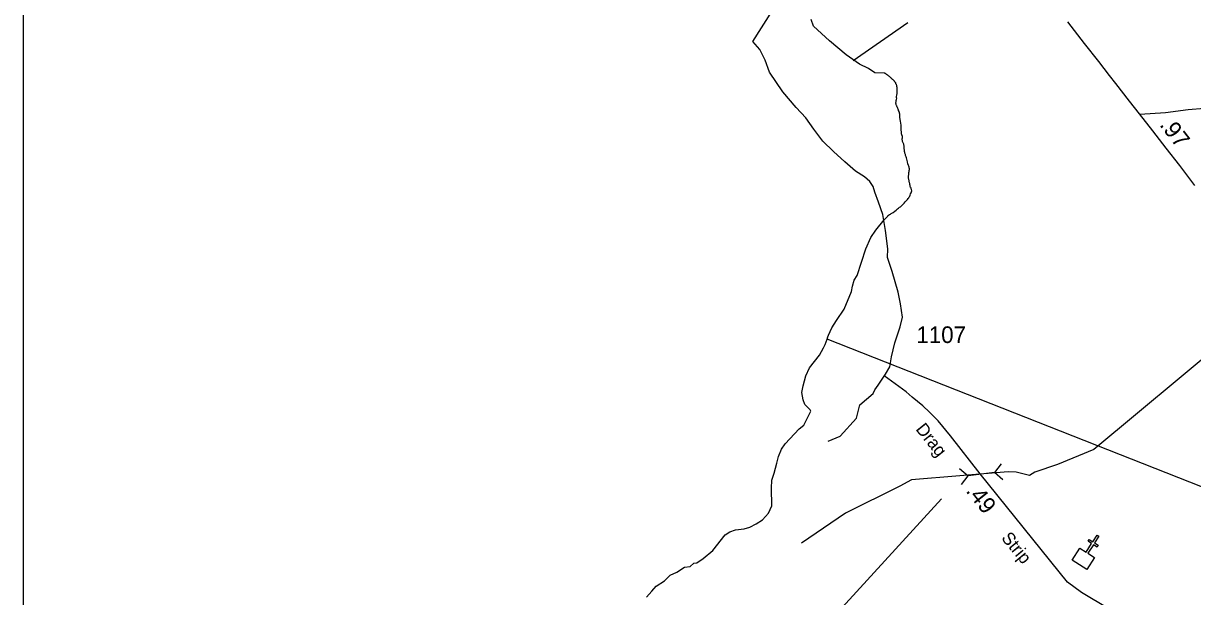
# Model space of a CAD drawing. Extents: x 2082433 to 2279600, y 546599 to 755198.
# Drawn here: x 2133614 to 2142394, y 575060 to 579366 of the extents above; entities that cross this region are included whole.
import ezdxf

# ---------------------------------------------------------------- set-up
doc = ezdxf.new("R2010")
doc.units = 0
for name, color, linetype in [('Exist Boundary Political CountyLine', 7, 'Continuous'), ('Exist Boundary Political Fire Districts', 7, 'Continuous'), ('Exist Cultural Church CELL', 7, 'Continuous'), ('Exist Hydrographic Creek Single Shore', 7, 'Continuous'), ('Exist Road Non-System Type 51', 7, 'Continuous'), ('Exist Road Primary NC Attributed', 7, 'Continuous'), ('Exist Road Primary NC Service Mileage Hundredths English Label', 7, 'Continuous'), ('Exist Road Secondary Mileage Hundredths English Label', 7, 'Continuous'), ('Exist Road Secondary Structure Culvert CELL', 7, 'Continuous'), ('Exist Road Secondary Structure Culvert Number Label', 7, 'Continuous'), ('Exist Road Secondary Type 51 Attributed', 7, 'Continuous'), ('Exist Road Secondary Type 51 Label', 7, 'Continuous'), ('Exist Road Secondary Type 51 Number Label', 7, 'Continuous'), ('Map Preparation Inset Cut Line', 7, 'Continuous')]:
    doc.layers.add(name, color=color, linetype=linetype)

msp = doc.modelspace()

# ---------------------------------------------------------------- linework, layer by layer
at = {"layer": 'Exist Boundary Political CountyLine'}
for points in [[(2139994.3, 578141.5), (2139970.9, 578177.9), (2139929.3, 578214.3), (2139862.6, 578255.7), (2139782.5, 578326.1), (2139696.7, 578404.1), (2139616.2, 578482.1), (2139548.6, 578570.5), (2139488.9, 578656.3), (2139416.1, 578734.3), (2139317.4, 578851.3), (2139216, 578999.5), (2139184.8, 579090.5), (2139143.3, 579168.5), (2139092.6, 579230.9), (2139238.1, 579462.3)], [(2140086.6, 576731), (2140119, 576786.9), (2140132, 576862.3), (2140158, 576966.3), (2140196.9, 577085.9), (2140215.1, 577158.7), (2140200.8, 577260.1), (2140182.6, 577345.9), (2140138.5, 577501.9), (2140103.4, 577608.5), (2140106, 577673.5), (2140087.8, 577811.3), (2140067, 577930.9), (2140035.8, 578021.9), (2140007.2, 578097.3), (2139994.3, 578141.5)], [(2139657.6, 576226.7), (2139746.8, 576266.1), (2139870.1, 576400.1), (2139895.1, 576499.9), (2139994.4, 576586.2), (2140007.7, 576612.2), (2140031.5, 576649.6), (2140086.6, 576731)]]:
    msp.add_lwpolyline(points, dxfattribs=at)
at = {"layer": 'Exist Boundary Political Fire Districts'}
for points in [[(2148987.7, 588267), (2148853.6, 588086.8), (2148166.4, 587162.7), (2149373.8, 581288.4), (2142989.3, 575675.9), (2139650, 576994.9)], [(2140124.1, 578960.3), (2140120.2, 578963.1), (2140116.5, 578966.2), (2140112.8, 578969.4), (2140110.8, 578971.5), (2140108.5, 578973.5), (2140105.8, 578975.8), (2140103, 578977.9), (2140100.7, 578979.5), (2140098.5, 578981.1), (2140096, 578982.8), (2140093.3, 578984.5), (2140090.7, 578986.2), (2140088, 578988.1), (2140085.9, 578989.1), (2140082.3, 578990.8), (2140079.2, 578992.1), (2140076.5, 578992.3), (2140006.8, 578993.3), (2139960.7, 579026.1), (2139893.4, 579059.7), (2139791.5, 579130.1), (2139666.2, 579233.7), (2139547.7, 579345.7), (2139528.4, 579395)], [(2140227, 578446), (2140226.4, 578451.9), (2140225.2, 578458), (2140222.9, 578464.4), (2140220.5, 578468.9), (2140218, 578472.9), (2140215.9, 578477.6), (2140214.7, 578483.1), (2140214.3, 578484.9), (2140213.7, 578491.5), (2140213.7, 578498), (2140214.3, 578506.7), (2140214.1, 578515.4), (2140212, 578523.2), (2140210.8, 578525.8), (2140210, 578527.6), (2140207.9, 578537.3), (2140207.5, 578545.1), (2140207.3, 578552.5), (2140206.5, 578558.9), (2140205.7, 578565.9), (2140205.1, 578573.3), (2140204.7, 578577.4), (2140205.1, 578581.4), (2140205.1, 578591.6), (2140205.3, 578596.2), (2140205.3, 578600.5), (2140199.5, 578630.6), (2140195.9, 578658.1), (2140195.2, 578680.5), (2140195.2, 578682.9), (2140195, 578684.9), (2140193.8, 578691.6), (2140192.6, 578696.2), (2140191.3, 578700.1), (2140189.1, 578705), (2140186.4, 578710.2), (2140184.6, 578715.3), (2140183.8, 578718.5), (2140182.7, 578721.9), (2140181.3, 578726.1), (2140179.2, 578730.1), (2140177.2, 578733.2), (2140175.8, 578736.1), (2140174.5, 578739.1), (2140173.5, 578742.3), (2140172.5, 578745.3), (2140170.4, 578749.5), (2140168.8, 578754.1), (2140167.3, 578759.8), (2140166.3, 578766.3), (2140165.9, 578771.8), (2140166.5, 578776.9), (2140168.6, 578786), (2140170.8, 578795.2), (2140171.7, 578803.4), (2140171.4, 578807), (2140171.2, 578811.1), (2140171.2, 578816.2), (2140173.1, 578827.6), (2140173.7, 578832.6), (2140174.3, 578837.6), (2140174.5, 578842.7), (2140174.5, 578851.7), (2140174.7, 578857.3), (2140174.9, 578864.2), (2140175.6, 578870.1), (2140175.8, 578874.7), (2140175.8, 578879.4), (2140175.3, 578882.9), (2140174.5, 578886.4), (2140173.9, 578889.4), (2140173.1, 578893.4), (2140171.7, 578898.1), (2140170, 578903.4), (2140169, 578906.1), (2140168.2, 578908.4), (2140167.3, 578910.6), (2140166.3, 578912.6), (2140165.1, 578915.5), (2140164.1, 578918.2), (2140162.4, 578921), (2140161, 578922.9), (2140159.6, 578924.3), (2140157.9, 578925.8), (2140157.1, 578927.3), (2140156.1, 578928.9), (2140154, 578932), (2140152.2, 578933.8), (2140149.7, 578936.2), (2140146.8, 578939.5), (2140144.6, 578942.3), (2140141.9, 578944.6), (2140140.5, 578945.4), (2140138, 578947), (2140136, 578949.3), (2140134.5, 578951), (2140130.4, 578955.1), (2140127.2, 578957.9), (2140124.1, 578960.3)], [(2139650, 576994.9), (2139655.7, 577010.5), (2139659.4, 577023.4), (2139684.5, 577079.1), (2139719.7, 577134.3), (2139778.2, 577218.4), (2139833.5, 577352.8), (2139840.3, 577392.9), (2139853.4, 577436), (2139874.3, 577472.5), (2139940.2, 577671.8), (2139977.1, 577757.4), (2140015, 577811.9), (2140076.5, 577890.3), (2140077.7, 577891.5), (2140082, 577895.3), (2140086.8, 577899.8), (2140093.7, 577906.4), (2140099.7, 577912.2), (2140104.4, 577917.4), (2140106.2, 577919.4), (2140108.3, 577921.6), (2140111.2, 577924.2), (2140118.5, 577929.7), (2140124.3, 577933.4), (2140130.8, 577937.4), (2140144.2, 577946.1), (2140156.5, 577954.2), (2140166.9, 577962.6), (2140170.8, 577966.1), (2140172.3, 577967.4), (2140177.8, 577972.8), (2140184.6, 577978.6), (2140192.8, 577984.5), (2140200, 577988.9), (2140207.3, 577994.2), (2140208.8, 577995.4), (2140211.2, 577997.8), (2140216.2, 578003.2), (2140221.3, 578009.1), (2140227.2, 578016.2), (2140236.2, 578026.1), (2140243.8, 578033.9), (2140251.8, 578043), (2140257.2, 578049.9), (2140262.1, 578056.3), (2140266, 578062.6), (2140269.3, 578069), (2140271.9, 578076.1), (2140275.2, 578084.6), (2140279.3, 578093.4), (2140283, 578100.9), (2140284.2, 578109.1), (2140282.8, 578118.4), (2140279.5, 578126.9), (2140276.2, 578135.1), (2140274, 578141.6), (2140271.9, 578148.6), (2140270.3, 578156.7), (2140269.1, 578163), (2140268, 578168.4), (2140266, 578180.5), (2140265, 578186.4), (2140263.7, 578191.9), (2140262.3, 578196), (2140260.9, 578200.4), (2140259.8, 578205.9), (2140259.8, 578211.8), (2140260.4, 578216.8), (2140261.3, 578222.3), (2140262.1, 578228.6), (2140262.5, 578234.3), (2140262.9, 578239.5), (2140263.9, 578245.7), (2140265, 578252.4), (2140265.8, 578260.3), (2140266.6, 578267.9), (2140267, 578274.4), (2140266, 578281.1), (2140264.3, 578286.9), (2140262.1, 578292.1), (2140260, 578297.1), (2140255.5, 578311.6), (2140252, 578327.1), (2140247.7, 578344.7), (2140244.7, 578355.5), (2140241.8, 578364.6), (2140238.5, 578374.7), (2140236.7, 578380.3), (2140235.2, 578385.4), (2140233.8, 578390.4), (2140232.4, 578396.8), (2140230.9, 578403.6), (2140229.7, 578411.2), (2140229.1, 578416.4), (2140228.5, 578421.1), (2140228, 578426.4), (2140227.4, 578433.5), (2140227.2, 578439.9), (2140227, 578446)], [(2138293, 575055.4), (2138334, 575100.6), (2138366.2, 575137.8), (2138427.3, 575179), (2138471.2, 575221.9), (2138522, 575243.5), (2138578.4, 575281.5), (2138620.8, 575287.1), (2138647.7, 575312.7), (2138671.7, 575315.1), (2138718.7, 575346), (2138791, 575405.6), (2138883.7, 575523.7), (2138919, 575547.4), (2138961.8, 575561.8), (2139025.2, 575569.8), (2139069.1, 575581.5), (2139116.3, 575606.6), (2139163, 575637.4), (2139210.2, 575686.3), (2139234.2, 575742), (2139231.7, 575874), (2139234.6, 575934.8), (2139251.8, 575986.4), (2139271.1, 576061.7), (2139285, 576112.9), (2139305.7, 576168.1), (2139334.2, 576208.2), (2139438.2, 576320.6), (2139475.5, 576347.9), (2139528.2, 576453.1), (2139520.8, 576463.9), (2139483.1, 576503.1), (2139468.5, 576537.6), (2139459.7, 576592.8), (2139469.6, 576642.4), (2139489, 576719.2), (2139517.7, 576778.5), (2139553.4, 576825.7), (2139591.6, 576872.9), (2139621.5, 576927.8), (2139634.8, 576953.7), (2139650, 576994.9)]]:
    msp.add_lwpolyline(points, dxfattribs=at)
at = {"layer": 'Exist Cultural Church CELL'}
msp.add_lwpolyline([(2141546.4, 575424.8), (2141594.4, 575394.2), (2141635.4, 575458.3), (2141608.5, 575475.6), (2141617.1, 575489), (2141644, 575471.8), (2141676.4, 575522.5), (2141689.9, 575513.8), (2141657.5, 575463.2), (2141684.5, 575445.9), (2141675.9, 575432.5), (2141648.9, 575449.7), (2141607.9, 575385.6), (2141656.4, 575354.4), (2141599.1, 575264.7), (2141489.1, 575335.1)], close=True, dxfattribs=at)
at = {"layer": 'Exist Hydrographic Creek Single Shore'}
for points in [[(2139844.6, 579086.3), (2140255.6, 579372.2)], [(2142621.4, 576970.8), (2141652.6, 576165.4), (2141378.7, 576052.8), (2141209, 575994.1), (2141168.3, 575970.5), (2141069.8, 575994.1), (2141007.6, 575998.1), (2140283.6, 575937.3), (2140196.5, 575889.7), (2139788.4, 575687.9), (2139456.8, 575462)]]:
    msp.add_lwpolyline(points, dxfattribs=at)
at = {"layer": 'Exist Road Non-System Type 51'}
msp.add_lwpolyline([(2141998.4, 578682.9), (2142190.9, 578696.8), (2142359.9, 578720.1), (2142482.4, 578728.5)], dxfattribs=at)
at = {"layer": 'Exist Road Primary NC Attributed'}
msp.add_lwpolyline([(2142410.9, 578149), (2142297.7, 578297.4), (2142195.6, 578429.5), (2142095.1, 578559.7), (2141994.8, 578687.3), (2141920.6, 578782), (2141816.7, 578914.1), (2141769.5, 578974.7), (2141689.1, 579078.4), (2141582.4, 579215.9), (2141456.6, 579376.6)], dxfattribs=at)
at = {"layer": 'Exist Road Secondary Structure Culvert CELL'}
for p, q in [((2140954.9, 576058), (2140905, 575991.3)), ((2140644.1, 576022), (2140707.9, 575968.5)), ((2140658, 575901.9), (2140707.9, 575968.5)), ((2140905, 575991.3), (2140707.9, 575968.5)), ((2140968.8, 575937.8), (2140905, 575991.3))]:
    msp.add_line(p, q, dxfattribs=at)
at = {"layer": 'Exist Road Secondary Structure Culvert Number Label'}
msp.add_line((2140508.4, 575793.7), (2139525.2, 574721.1), dxfattribs=at)
at = {"layer": 'Exist Road Secondary Type 51 Attributed'}
msp.add_lwpolyline([(2141765.3, 574969.7), (2141560.2, 575092.4), (2141453.1, 575169.5), (2140798.8, 575983.3), (2140576.1, 576268.2), (2140481.9, 576379.6), (2140417.6, 576446), (2140368.4, 576493.1), (2140289.1, 576557.3), (2140243, 576599.5), (2140077.9, 576718.1)], dxfattribs=at)
at = {"layer": 'Map Preparation Inset Cut Line'}
msp.add_lwpolyline([(2133614.2, 585979.7), (2209297.4, 585979.7), (2209297.4, 557274.4), (2194088.6, 557271.1), (2194088.6, 546598.7), (2133614.2, 546598.7)], close=True, dxfattribs=at)

# ---------------------------------------------------------------- texts
at = {"layer": 'Exist Road Primary NC Service Mileage Hundredths English Label'}
msp.add_text('.97', height=125, rotation=307.66689, dxfattribs=at).set_placement((2142141.1, 578602.3))
at = {"layer": 'Exist Road Secondary Mileage Hundredths English Label'}
msp.add_text('.49', height=125, rotation=308.21013, dxfattribs=at).set_placement((2140686.3, 575852.7))
at = {"layer": 'Exist Road Secondary Type 51 Label'}
for s, rotation, p in [('Drag', 308.79223, (2140309.8, 576316.4)), ('Strip', 309.51587, (2140952.4, 575498.3))]:
    msp.add_text(s, height=95, rotation=rotation, dxfattribs=at).set_placement(p)
at = {"layer": 'Exist Road Secondary Type 51 Number Label'}
msp.add_text('1107', height=125, dxfattribs=at).set_placement((2140320.1, 576965))

doc.saveas('drawing.dxf')
